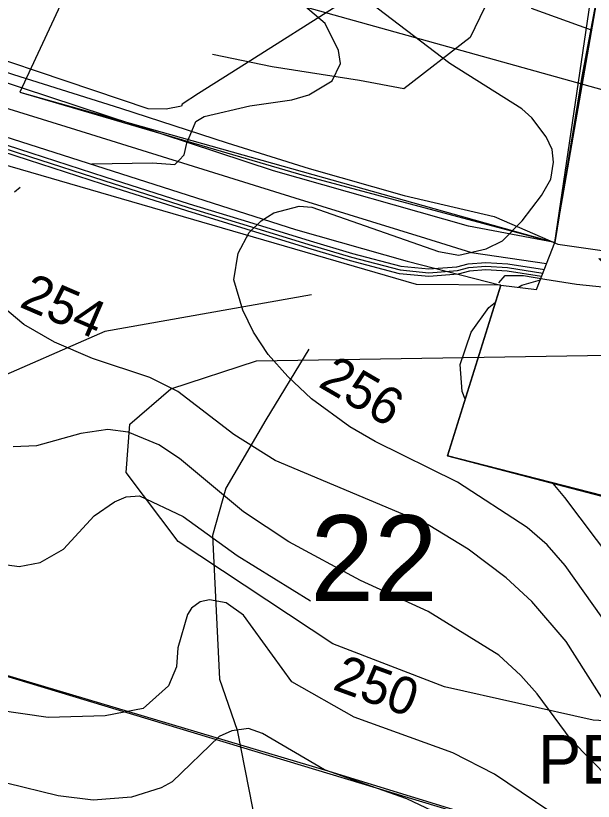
# Model space of a CAD drawing. Extents: x -662500 to -655523, y -1056000 to -1049993.
# Drawn here: x -660694.1 to -660539, y -1052282.8 to -1052071.9 of the extents above; entities that cross this region are included whole.
import ezdxf

# ---------------------------------------------------------------- set-up
doc = ezdxf.new("R2010")
doc.units = 0
for name, color, linetype in [('63LINIE', 7, 'Continuous'), ('Vrstva 1', 7, 'Continuous'), ('Vrstva 20', 7, 'Continuous'), ('Vrstva 22', 7, 'Continuous'), ('Vrstva 24', 7, 'Continuous'), ('Vrstva 42', 7, 'Continuous'), ('Vrstva 45', 7, 'Continuous'), ('Vrstva 47', 7, 'Continuous'), ('Vrstva 5', 7, 'Continuous'), ('Vrstva 57', 7, 'Continuous'), ('Vrstva 6', 7, 'Continuous'), ('Vrstva 7', 7, 'Continuous')]:
    doc.layers.add(name, color=color, linetype=linetype)

msp = doc.modelspace()

# ---------------------------------------------------------------- linework, layer by layer
at = {"layer": '63LINIE'}
msp.add_lwpolyline([(-661089.92, -1052023.41), (-661033.05, -1052031.56), (-660920.35, -1052046.48), (-660821, -1052060.23), (-660803.07, -1052062.71), (-660768.57, -1052074.37), (-660678.06, -1052102.44), (-660619.13, -1052120.72), (-660584.07, -1052131.59), (-660571.71, -1052135.42), (-660551.54, -1052138.42)], dxfattribs=at)
at = {"layer": 'Vrstva 1'}
for points in [[(-660554.23, -1052145.33), (-660549.33, -1052132.73), (-660543.74, -1052100.07), (-660537.55, -1052064.32), (-660536.99, -1052061.08), (-660533.42, -1052042.18), (-660529.4, -1052017.99), (-660526.37, -1052016.17), (-660497.13, -1051998.48), (-660473.03, -1051983.91), (-660444.41, -1051966.62), (-660443.04, -1051941.53), (-660409.35, -1051945.41), (-660388.98, -1051947.77), (-660362.03, -1051950.34), (-660358.34, -1051950.81), (-660318.47, -1051954.21), (-660286.74, -1051956.91), (-660259.81, -1051958.85)], [(-660495.07, -1052211.29), (-660517.03, -1052205.91), (-660527.17, -1052203.32), (-660534.27, -1052201.47), (-660536.66, -1052200.85), (-660578.14, -1052190.03), (-660572.16, -1052170.84), (-660563.85, -1052144.19), (-660554.23, -1052145.33)]]:
    msp.add_lwpolyline(points, dxfattribs=at)
at = {"layer": 'Vrstva 20'}
for points in [[(-660693, -1052092.39), (-660549.33, -1052132.73), (-660529.4, -1052017.99), (-660444.65, -1051966.93), (-660443.04, -1051941.53), (-660507.57, -1051940.01), (-660528.33, -1051935.72), (-660624.47, -1051996.3), (-660674.23, -1052051.96)], [(-660611.17, -1052274.32), (-660487.99, -1052312.15), (-660486.82, -1052314.01), (-660462.36, -1052329.02), (-660459.17, -1052336.8), (-660433.93, -1052352.12), (-660408.77, -1052283.62), (-660402.29, -1052259.33), (-660394.65, -1052237.63), (-660389.99, -1052217.3), (-660417.67, -1052208.59), (-660428.58, -1052243.68), (-660475.36, -1052232.69), (-660499.48, -1052225.45), (-660495.07, -1052211.29), (-660578.14, -1052190.03), (-660563.85, -1052144.19), (-660586.5, -1052144.05), (-660704.06, -1052109.9), (-660743.35, -1052235.04)]]:
    msp.add_lwpolyline(points, close=True, dxfattribs=at)
at = {"layer": 'Vrstva 22'}
msp.add_lwpolyline([(-661110.22, -1052170.21), (-661096.01, -1052128.52), (-660487.99, -1052312.15), (-660506.09, -1052352.23)], close=True, dxfattribs=at)
at = {"layer": 'Vrstva 24'}
for points in [[(-660328, -1052135), (-660352, -1052135.5), (-660451.5, -1052115.5), (-660661, -1052057), (-660695, -1052042.5), (-660723, -1052024.5), (-660747.5, -1052000), (-660756.5, -1051991), (-660777.56, -1051972.71)], [(-660417.5, -1052245), (-660451.5, -1052250.5), (-660478, -1052259), (-660504, -1052263), (-660539, -1052261), (-660579, -1052252), (-660609, -1052240.5), (-660650.5, -1052213), (-660664.5, -1052194.5), (-660663.5, -1052181.5), (-660652.5, -1052172), (-660629.5, -1052164.5), (-660535, -1052163), (-660529, -1052158), (-660526, -1052149), (-660537.5, -1052137), (-660493, -1052145), (-660399.5, -1052152)]]:
    msp.add_lwpolyline(points, dxfattribs=at)
at = {"layer": 'Vrstva 42'}
msp.add_line((-660572.44, -1052139.42), (-660567.9, -1052139.12), dxfattribs=at)
for points in [[(-660806.43, -1052073.46), (-660805.97, -1052073.55), (-660786.17, -1052078.32), (-660768.37, -1052083.66), (-660748.27, -1052090.89), (-660690.41, -1052109.64), (-660670.47, -1052116.09), (-660647.85, -1052123.31), (-660631.93, -1052128.18), (-660615.37, -1052133.26), (-660603.98, -1052136.67), (-660590.91, -1052140.12), (-660583.21, -1052140.84), (-660575.46, -1052140.25), (-660572.44, -1052139.42)], [(-660567.9, -1052139.12), (-660562.03, -1052139.45), (-660552.53, -1052140.95)]]:
    msp.add_lwpolyline(points, dxfattribs=at)
at = {"layer": 'Vrstva 45'}
for points in [[(-660354.85, -1051915.03), (-660355.57, -1051915.05), (-660360.53, -1051915.59), (-660365.86, -1051916.12), (-660370.11, -1051918.64), (-660403.89, -1051941.33), (-660431.8, -1051959.98), (-660437.63, -1051964.09), (-660456.56, -1051977.17), (-660464.14, -1051981.81), (-660471.08, -1051986.06), (-660504.84, -1052003.55), (-660517.9, -1052011.55), (-660544.46, -1052028.03), (-660604.39, -1052067), (-660634.41, -1052086), (-660645.04, -1052092.71), (-660649.43, -1052095.57), (-660649.65, -1052096.13), (-660653.7, -1052096.98), (-660658.56, -1052096.83), (-660725, -1052074.48)], [(-660354.85, -1051915.03), (-660355.57, -1051915.05), (-660360.53, -1051915.59), (-660365.86, -1051916.12), (-660370.11, -1051918.64), (-660403.89, -1051941.33), (-660431.8, -1051959.98), (-660437.63, -1051964.09), (-660456.56, -1051977.17), (-660464.14, -1051981.81), (-660471.08, -1051986.06), (-660504.84, -1052003.55), (-660517.9, -1052011.55), (-660544.46, -1052028.03), (-660604.39, -1052067), (-660634.41, -1052086), (-660645.04, -1052092.71), (-660649.43, -1052095.57), (-660649.65, -1052096.13), (-660653.7, -1052096.98), (-660658.56, -1052096.83), (-660725, -1052074.48)], [(-660354.85, -1051915.03), (-660355.57, -1051915.05), (-660360.53, -1051915.59), (-660365.86, -1051916.12), (-660370.11, -1051918.64), (-660403.89, -1051941.33), (-660431.8, -1051959.98), (-660437.63, -1051964.09), (-660456.56, -1051977.17), (-660464.14, -1051981.81), (-660471.08, -1051986.06), (-660504.84, -1052003.55), (-660517.9, -1052011.55), (-660544.46, -1052028.03), (-660604.39, -1052067), (-660634.41, -1052086), (-660645.04, -1052092.71), (-660649.43, -1052095.57), (-660649.65, -1052096.13), (-660653.7, -1052096.98), (-660658.56, -1052096.83), (-660725, -1052074.48)], [(-660354.85, -1051915.03), (-660355.57, -1051915.05), (-660360.53, -1051915.59), (-660365.86, -1051916.12), (-660370.11, -1051918.64), (-660403.89, -1051941.33), (-660431.8, -1051959.98), (-660437.63, -1051964.09), (-660456.56, -1051977.17), (-660464.14, -1051981.81), (-660471.08, -1051986.06), (-660504.84, -1052003.55), (-660517.9, -1052011.55), (-660544.46, -1052028.03), (-660604.39, -1052067), (-660634.41, -1052086), (-660645.04, -1052092.71), (-660649.43, -1052095.57), (-660649.65, -1052096.13), (-660653.7, -1052096.98), (-660658.56, -1052096.83), (-660725, -1052074.48)], [(-660354.85, -1051915.03), (-660355.57, -1051915.05), (-660360.53, -1051915.59), (-660365.86, -1051916.12), (-660370.11, -1051918.64), (-660403.89, -1051941.33), (-660431.8, -1051959.98), (-660437.63, -1051964.09), (-660456.56, -1051977.17), (-660464.14, -1051981.81), (-660471.08, -1051986.06), (-660504.84, -1052003.55), (-660517.9, -1052011.55), (-660544.46, -1052028.03), (-660604.39, -1052067), (-660634.41, -1052086), (-660645.04, -1052092.71), (-660649.43, -1052095.57), (-660649.65, -1052096.13), (-660653.7, -1052096.98), (-660658.56, -1052096.83), (-660725, -1052074.48)], [(-660354.85, -1051915.03), (-660355.57, -1051915.05), (-660360.53, -1051915.59), (-660365.86, -1051916.12), (-660370.11, -1051918.64), (-660403.89, -1051941.33), (-660431.8, -1051959.98), (-660437.63, -1051964.09), (-660456.56, -1051977.17), (-660464.14, -1051981.81), (-660471.08, -1051986.06), (-660504.84, -1052003.55), (-660517.9, -1052011.55), (-660544.46, -1052028.03), (-660604.39, -1052067), (-660634.41, -1052086), (-660645.04, -1052092.71), (-660649.43, -1052095.57), (-660649.65, -1052096.13), (-660653.7, -1052096.98), (-660658.56, -1052096.83), (-660725, -1052074.48)], [(-660830.25, -1052048.16), (-660801.6, -1052052.43), (-660785.76, -1052056.82), (-660749.53, -1052069.14), (-660722.87, -1052078.18), (-660694.73, -1052087.6), (-660666.02, -1052096.71), (-660637.38, -1052105.99), (-660615.28, -1052112.88), (-660589.8, -1052120.12), (-660565.6, -1052125.72)], [(-660830.25, -1052048.16), (-660801.6, -1052052.43), (-660785.76, -1052056.82), (-660749.53, -1052069.14), (-660722.87, -1052078.18), (-660694.73, -1052087.6), (-660666.02, -1052096.71), (-660637.38, -1052105.99), (-660615.28, -1052112.88), (-660589.8, -1052120.12), (-660565.6, -1052125.72)], [(-660565.6, -1052125.72), (-660548.55, -1052133.15), (-660522.21, -1052136.92), (-660520.4, -1052135.15), (-660516.13, -1052135.6)], [(-660565.6, -1052125.72), (-660548.55, -1052133.15), (-660522.21, -1052136.92), (-660520.4, -1052135.15), (-660516.13, -1052135.6)], [(-660564.37, -1052143.61), (-660562.65, -1052141.61), (-660557.78, -1052141.59), (-660552.06, -1052142.58), (-660543.55, -1052143.9), (-660533.12, -1052144.98), (-660530.51, -1052145.48), (-660529.78, -1052145.27), (-660526.61, -1052145.69), (-660521.94, -1052146.63), (-660518.89, -1052146.94)], [(-660564.37, -1052143.61), (-660562.65, -1052141.61), (-660557.78, -1052141.59), (-660552.06, -1052142.58), (-660543.55, -1052143.9), (-660533.12, -1052144.98), (-660530.51, -1052145.48), (-660529.78, -1052145.27), (-660526.61, -1052145.69), (-660521.94, -1052146.63), (-660518.89, -1052146.94)]]:
    msp.add_lwpolyline(points, dxfattribs=at)
at = {"layer": 'Vrstva 47'}
for points in [[(-660747.95, -1052089.94), (-660690.1, -1052108.69), (-660670.16, -1052115.14), (-660647.55, -1052122.36), (-660631.64, -1052127.22), (-660615.08, -1052132.3), (-660603.71, -1052135.7), (-660590.73, -1052139.13), (-660583.2, -1052139.84), (-660575.63, -1052139.26), (-660572.61, -1052138.43), (-660567.9, -1052138.11), (-660561.92, -1052138.46), (-660552.15, -1052139.99)], [(-660552.9, -1052141.9), (-660562.13, -1052140.45), (-660567.89, -1052140.12), (-660572.28, -1052140.41), (-660575.29, -1052141.24), (-660583.22, -1052141.85), (-660591.09, -1052141.11), (-660604.25, -1052137.63), (-660615.66, -1052134.22), (-660632.22, -1052129.14), (-660648.14, -1052124.27), (-660670.78, -1052117.04), (-660690.71, -1052110.59), (-660748.59, -1052091.84)]]:
    msp.add_lwpolyline(points, dxfattribs=at)
at = {"layer": 'Vrstva 5'}
for points in [[(-660415.51, -1051792.48), (-660387.33, -1051842.39), (-660368.51, -1051881.97), (-660363.96, -1051894.27), (-660362.05, -1051903.98), (-660361.48, -1051911.34), (-660361.47, -1051915.93), (-660361.97, -1051944.48), (-660362.03, -1051950.34), (-660388.98, -1051947.77), (-660443.04, -1051941.53), (-660444.41, -1051966.62), (-660473.03, -1051983.91), (-660497.13, -1051998.48), (-660529.4, -1052017.99), (-660533.42, -1052042.18), (-660542.09, -1052088.13), (-660549.33, -1052132.73), (-660572.52, -1052128.33), (-660624.87, -1052113.48), (-660745.13, -1052073.98)], [(-660757.57, -1052084.94), (-660618.97, -1052129.25), (-660588.97, -1052137.76), (-660563.85, -1052144.19), (-660554.23, -1052145.33), (-660549.33, -1052132.73), (-660572.52, -1052128.33), (-660624.87, -1052113.48), (-660745.13, -1052073.98)], [(-660757.57, -1052084.94), (-660618.97, -1052129.25), (-660588.97, -1052137.76), (-660563.85, -1052144.19), (-660578.14, -1052190.03), (-660527.17, -1052203.32), (-660495.07, -1052211.29), (-660499.48, -1052225.45), (-660497.36, -1052226.43), (-660475.36, -1052232.69), (-660428.58, -1052243.68), (-660421.03, -1052221.2), (-660417.67, -1052208.59), (-660396.18, -1052215.3), (-660389.99, -1052217.3), (-660394.65, -1052237.63), (-660402.29, -1052259.33), (-660408.77, -1052283.62)]]:
    msp.add_lwpolyline(points, dxfattribs=at)
at = {"layer": 'Vrstva 57'}
for points in [[(-660519.42, -1051968.67), (-660572.05, -1052077.71), (-660589.91, -1052091.45), (-660601.78, -1052089.22), (-660625.28, -1052085.58), (-660641.26, -1052082.29)], [(-660614.7, -1052146.79), (-660670.16, -1052156.66), (-660702.59, -1052170.76), (-660725.62, -1052188.62), (-660759.45, -1052215.88), (-660863.32, -1052358.75)], [(-660615.41, -1052161.36), (-660626.92, -1052180.39), (-660637.73, -1052198.72), (-660641.26, -1052211.41), (-660639.38, -1052249.95), (-660634.68, -1052263.7), (-660630.57, -1052284.61), (-660627.61, -1052306.06), (-660626.81, -1052332.78), (-660627.04, -1052339.48), (-660634.33, -1052360.39), (-660644.19, -1052384.83), (-660659.7, -1052407.15), (-660752.84, -1052470.52)]]:
    msp.add_lwpolyline(points, dxfattribs=at)
at = {"layer": 'Vrstva 6'}
msp.add_lwpolyline([(-660717.09, -1051942.16), (-660678.48, -1051976.85), (-660636.23, -1052006.19), (-660634.2, -1052007.19), (-660674.23, -1052051.96), (-660693, -1052092.39), (-660616.69, -1052114.74), (-660549.33, -1052132.73), (-660535.03, -1052035.66), (-660529.4, -1052017.99), (-660444.79, -1051966.85), (-660443.04, -1051941.53), (-660507.57, -1051940.01), (-660528.33, -1051935.72), (-660624.47, -1051996.3), (-660625.14, -1051997.08), (-660628.82, -1051995.51), (-660670.4, -1051966.64), (-660708.78, -1051932.15)], dxfattribs=at)
msp.add_lwpolyline([(-660462.36, -1052329.02), (-660459.17, -1052336.8), (-660433.93, -1052352.12), (-660409.6, -1052285.62), (-660402.29, -1052259.33), (-660394.65, -1052237.63), (-660389.99, -1052217.3), (-660417.67, -1052208.59), (-660421.03, -1052221.2), (-660428.58, -1052243.68), (-660452.47, -1052238.38), (-660475.36, -1052232.69), (-660499.48, -1052225.45), (-660495.07, -1052211.29), (-660578.14, -1052190.03), (-660563.85, -1052144.19), (-660586.5, -1052144.05), (-660704.06, -1052109.9), (-660743.35, -1052235.04), (-661096.01, -1052128.52), (-661110.22, -1052170.21), (-660506.09, -1052352.23), (-660487.99, -1052312.15)], close=True, dxfattribs=at)
at = {"layer": 'Vrstva 7'}
for p, q in [((-660577.58, -1052084.7), (-660618.82, -1052053.1)), ((-660611.03, -1052073.93), (-660621.66, -1052064.86)), ((-660539.53, -1052075.76), (-660555.61, -1052069.96)), ((-660607.48, -1052081.16), (-660611.03, -1052073.93)), ((-660606.92, -1052084.7), (-660607.48, -1052081.16)), ((-660609.18, -1052089.38), (-660606.92, -1052084.7)), ((-660558.17, -1052096.89), (-660577.58, -1052084.7)), ((-660615.42, -1052093.06), (-660609.18, -1052089.38)), ((-660631.29, -1052096.04), (-660619.95, -1052094.48)), ((-660619.95, -1052094.48), (-660615.42, -1052093.06)), ((-660643.48, -1052098.87), (-660631.29, -1052096.04)), ((-660555.47, -1052099.3), (-660558.17, -1052096.89)), ((-660648.16, -1052106.1), (-660645.75, -1052100.29)), ((-660645.75, -1052100.29), (-660643.48, -1052098.87)), ((-660551.65, -1052104.4), (-660555.47, -1052099.3)), ((-660550.09, -1052107.8), (-660551.65, -1052104.4)), ((-660648.88, -1052109.24), (-660648.16, -1052106.1)), ((-660650.2, -1052110.62), (-660648.88, -1052109.24)), ((-660549.66, -1052111.2), (-660550.09, -1052107.8)), ((-660673.67, -1052111.66), (-660657.37, -1052111.34)), ((-660657.37, -1052111.34), (-660651.42, -1052111.84)), ((-660651.42, -1052111.84), (-660650.2, -1052110.62)), ((-660550.37, -1052115.74), (-660549.66, -1052111.2)), ((-660552.92, -1052120.13), (-660550.37, -1052115.74)), ((-660694.5, -1052119.14), (-660692.94, -1052117.84)), ((-660558.14, -1052126.93), (-660552.92, -1052120.13)), ((-660624.77, -1052124.8), (-660617.97, -1052122.96)), ((-660617.97, -1052122.96), (-660614.57, -1052123.25)), ((-660614.57, -1052123.25), (-660580.56, -1052135.15)), ((-660628.17, -1052126.93), (-660624.77, -1052124.8)), ((-660631.43, -1052130.05), (-660628.17, -1052126.93)), ((-660563.41, -1052132.32), (-660558.14, -1052126.93)), ((-660634.41, -1052135.57), (-660631.43, -1052130.05)), ((-660567.8, -1052134.44), (-660563.41, -1052132.32)), ((-660575.1, -1052136.14), (-660567.8, -1052134.44)), ((-660635.54, -1052142.8), (-660634.41, -1052135.57)), ((-660580.56, -1052135.15), (-660575.1, -1052136.14)), ((-660633.13, -1052150.88), (-660635.54, -1052142.8)), ((-660558.17, -1052144.22), (-660553.22, -1052142.74)), ((-660559.12, -1052144.75), (-660558.17, -1052144.22)), ((-660567.09, -1052150.17), (-660565.26, -1052148.72)), ((-660691.95, -1052154.71), (-660697.61, -1052150.03)), ((-660630.3, -1052156.83), (-660633.13, -1052150.88)), ((-660571.77, -1052156.83), (-660567.09, -1052150.17)), ((-660683.73, -1052159.53), (-660691.95, -1052154.71)), ((-660626.33, -1052162.78), (-660630.3, -1052156.83)), ((-660574.75, -1052165.48), (-660571.77, -1052156.83)), ((-660673.52, -1052163.92), (-660683.73, -1052159.53)), ((-660658.08, -1052169.02), (-660673.52, -1052163.92)), ((-660621.09, -1052168.74), (-660626.33, -1052162.78)), ((-660574.18, -1052172.71), (-660574.75, -1052165.48)), ((-660650.57, -1052172.71), (-660658.08, -1052169.02)), ((-660614.71, -1052174.69), (-660621.09, -1052168.74)), ((-660635.54, -1052184.33), (-660650.57, -1052172.71)), ((-660604.36, -1052182.2), (-660614.71, -1052174.69)), ((-660573.38, -1052174.76), (-660574.18, -1052172.71)), ((-660669.41, -1052182.91), (-660676.64, -1052184.04)), ((-660663.89, -1052183.62), (-660669.41, -1052182.91)), ((-660597.56, -1052186.17), (-660604.36, -1052182.2)), ((-660676.64, -1052184.04), (-660688.55, -1052187.3)), ((-660655.67, -1052187.02), (-660663.89, -1052183.62)), ((-660624.49, -1052191.27), (-660635.54, -1052184.33)), ((-660688.55, -1052187.3), (-660694.78, -1052187.59)), ((-660650.14, -1052190.7), (-660655.67, -1052187.02)), ((-660575.45, -1052197.08), (-660597.56, -1052186.17)), ((-660632.99, -1052205.02), (-660650.14, -1052190.7)), ((-660583.39, -1052208.56), (-660624.49, -1052191.27)), ((-660556.75, -1052209.27), (-660575.45, -1052197.08)), ((-660546.69, -1052201.19), (-660549.74, -1052197.44)), ((-660667.57, -1052202.32), (-660664.45, -1052201.05)), ((-660664.45, -1052201.05), (-660660.91, -1052200.77)), ((-660660.91, -1052200.77), (-660649.15, -1052206.29)), ((-660526.7, -1052227.69), (-660546.69, -1052201.19)), ((-660673.1, -1052206.15), (-660667.57, -1052202.32)), ((-660681.32, -1052215.08), (-660673.1, -1052206.15)), ((-660649.15, -1052206.29), (-660634.69, -1052216.78)), ((-660620.8, -1052213.09), (-660632.99, -1052205.02)), ((-660572.62, -1052215.08), (-660583.39, -1052208.56)), ((-660551.36, -1052213.95), (-660556.75, -1052209.27)), ((-660601.53, -1052223.44), (-660620.8, -1052213.09)), ((-660546.54, -1052219.47), (-660551.36, -1052213.95)), ((-660687.55, -1052218.62), (-660681.32, -1052215.08)), ((-660634.69, -1052216.78), (-660614.99, -1052228.97)), ((-660562.42, -1052222.73), (-660572.62, -1052215.08)), ((-660713.49, -1052216.92), (-660693.22, -1052219.76)), ((-660693.22, -1052219.76), (-660687.55, -1052218.62)), ((-660532.92, -1052238.69), (-660546.54, -1052219.47)), ((-660555.47, -1052229.11), (-660562.42, -1052222.73)), ((-660583.39, -1052231.8), (-660601.53, -1052223.44)), ((-660644.61, -1052229.25), (-660646.88, -1052230.95)), ((-660642.06, -1052228.68), (-660644.61, -1052229.25)), ((-660637.58, -1052229.48), (-660642.06, -1052228.68)), ((-660632.99, -1052232.79), (-660637.58, -1052229.48)), ((-660546.26, -1052239.88), (-660555.47, -1052229.11)), ((-660646.88, -1052230.95), (-660648.01, -1052232.65)), ((-660648.01, -1052232.65), (-660650.56, -1052241.58)), ((-660619.95, -1052250.65), (-660632.99, -1052232.79)), ((-660564.4, -1052243.56), (-660583.39, -1052231.8)), ((-660535.07, -1052257.45), (-660546.26, -1052239.88)), ((-660650.56, -1052241.58), (-660650.99, -1052246.68)), ((-660558.45, -1052248.95), (-660564.4, -1052243.56)), ((-660650.99, -1052246.68), (-660653.11, -1052251.78)), ((-660554.06, -1052253.91), (-660558.45, -1052248.95)), ((-660653.11, -1052251.78), (-660659.92, -1052257.88)), ((-660603.23, -1052260.14), (-660619.95, -1052250.65)), ((-660544.99, -1052266.24), (-660554.06, -1052253.91)), ((-660685.43, -1052260.29), (-660700.73, -1052258.02)), ((-660659.92, -1052257.88), (-660670.12, -1052259.86)), ((-660670.12, -1052259.86), (-660685.43, -1052260.29)), ((-660576.73, -1052269.78), (-660603.23, -1052260.14)), ((-660631.58, -1052263.26), (-660636.11, -1052263.83)), ((-660627.89, -1052264.54), (-660631.58, -1052263.26)), ((-660636.11, -1052263.83), (-660639.51, -1052265.39)), ((-660611.17, -1052274.32), (-660627.89, -1052264.54)), ((-660639.51, -1052265.39), (-660652.12, -1052277.58)), ((-660534.64, -1052276.73), (-660544.99, -1052266.24)), ((-660565.54, -1052275.45), (-660576.73, -1052269.78)), ((-660589.06, -1052282.11), (-660611.17, -1052274.32)), ((-660534.21, -1052296.56), (-660565.54, -1052275.45)), ((-660682.73, -1052281.26), (-660696.62, -1052277.86)), ((-660652.12, -1052277.58), (-660655.1, -1052279.13)), ((-660655.1, -1052279.13), (-660663.04, -1052281.69)), ((-660673.31, -1052282.46), (-660682.73, -1052281.26)), ((-660663.04, -1052281.69), (-660673.31, -1052282.46)), ((-660575.45, -1052288.49), (-660589.06, -1052282.11))]:
    msp.add_line(p, q, dxfattribs=at)

# ---------------------------------------------------------------- texts
at = {"layer": 'Vrstva 20'}
msp.add_text('PEO 9-OZ', height=13, dxfattribs=at).set_placement((-660553.86, -1052277.99))
at = {"layer": 'Vrstva 57'}
msp.add_text('22', height=23, dxfattribs=at).set_placement((-660614.99, -1052228.97))
at = {"layer": 'Vrstva 7'}
for s, rotation, p in [('254', 336.7052, (-660693.47, -1052149.89)), ('256', 329.7425, (-660613.2, -1052171.25)), ('250', 340.0164, (-660609.34, -1052252.6))]:
    msp.add_text(s, height=10, rotation=rotation, dxfattribs=at).set_placement(p)

doc.saveas('drawing.dxf')
